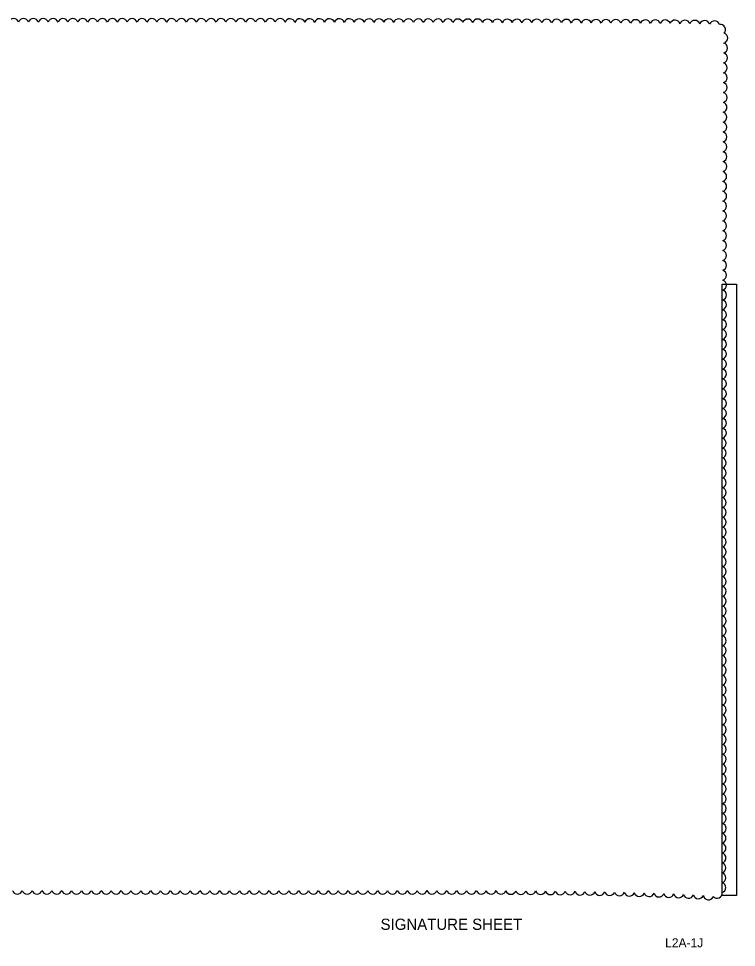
# Model space of a CAD drawing. Extents: x -811 to 10319, y -2309 to 9962.
# Drawn here: x -803.29 to -795.29, y -2309.09 to -2298.74 of the extents above; entities that cross this region are included whole.
import ezdxf

# ---------------------------------------------------------------- set-up
doc = ezdxf.new("R2010")
doc.units = 0
for name, color, linetype in [('AdhocPoint_dp', 7, 'Continuous'), ('PlotBorder_dp', 7, 'Continuous'), ('ScratchEle_dp', 7, 'Continuous'), ('SheetLines_dp', 7, 'Continuous')]:
    doc.layers.add(name, color=color, linetype=linetype)

msp = doc.modelspace()

# ---------------------------------------------------------------- linework, layer by layer
at = {"layer": 'AdhocPoint_dp'}
msp.add_lwpolyline([(-795.444, -2301.701), (-795.287, -2301.701), (-795.287, -2308.512), (-795.444, -2308.512)], close=True, dxfattribs=at)
at = {"layer": 'ScratchEle_dp'}
for centre, start, end in [((-803.344, -2298.801), 17.5, 162.5), ((-803.234, -2298.801), 17.5, 162.5), ((-803.124, -2298.801), 17.4999, 162.4999), ((-803.014, -2298.801), 17.4985, 162.4985), ((-802.904, -2298.801), 17.4968, 162.4968), ((-802.794, -2298.801), 17.495, 162.495), ((-802.684, -2298.801), 17.4932, 162.4932), ((-802.574, -2298.801), 17.4913, 162.4913), ((-802.464, -2298.801), 17.4894, 162.4894), ((-802.354, -2298.801), 17.4875, 162.4875), ((-802.243, -2298.801), 17.4855, 162.4855), ((-802.133, -2298.801), 17.4835, 162.4835), ((-802.023, -2298.801), 17.4814, 162.4814), ((-801.913, -2298.801), 17.4792, 162.4792), ((-801.803, -2298.801), 17.477, 162.477), ((-801.693, -2298.802), 17.4748, 162.4748), ((-801.583, -2298.802), 17.4725, 162.4725), ((-801.473, -2298.802), 17.4701, 162.4701), ((-801.363, -2298.802), 17.4676, 162.4676), ((-801.253, -2298.802), 17.4651, 162.4651), ((-801.143, -2298.802), 17.4625, 162.4625), ((-801.033, -2298.802), 17.4599, 162.4599), ((-800.923, -2298.802), 17.4571, 162.4571), ((-800.813, -2298.802), 17.4543, 162.4543), ((-800.703, -2298.802), 17.4514, 162.4514), ((-800.593, -2298.802), 17.4484, 162.4484), ((-800.483, -2298.802), 17.4453, 162.4453), ((-800.373, -2298.802), 17.4421, 162.4421), ((-800.263, -2298.803), 17.4388, 162.4388), ((-800.153, -2298.803), 17.4354, 162.4354), ((-800.043, -2298.803), 17.4318, 162.4318), ((-799.933, -2298.803), 17.4281, 162.4281), ((-799.823, -2298.803), 17.4243, 162.4243), ((-799.712, -2298.803), 17.4204, 162.4204), ((-799.602, -2298.803), 17.4162, 162.4162), ((-799.492, -2298.804), 17.412, 162.412), ((-799.382, -2298.804), 17.4075, 162.4075), ((-799.272, -2298.804), 17.4029, 162.4029), ((-799.162, -2298.804), 17.398, 162.398), ((-799.052, -2298.804), 17.3929, 162.3929), ((-798.942, -2298.805), 17.3876, 162.3876), ((-798.832, -2298.805), 17.3821, 162.3821), ((-798.722, -2298.805), 17.3762, 162.3762), ((-798.612, -2298.805), 17.3701, 162.3701), ((-798.502, -2298.805), 17.3636, 162.3636), ((-798.392, -2298.806), 17.3568, 162.3568), ((-798.282, -2298.806), 17.3496, 162.3496), ((-798.172, -2298.806), 17.342, 162.342), ((-798.062, -2298.807), 17.3339, 162.3339), ((-797.952, -2298.807), 17.3253, 162.3253), ((-797.842, -2298.807), 17.3161, 162.3161), ((-797.732, -2298.808), 17.3062, 162.3062), ((-797.622, -2298.808), 17.2956, 162.2956), ((-797.512, -2298.808), 17.2842, 162.2842), ((-797.402, -2298.809), 17.2719, 162.2719), ((-797.292, -2298.809), 17.2584, 162.2584), ((-797.182, -2298.81), 17.2438, 162.2438), ((-797.072, -2298.81), 17.2277, 162.2277), ((-796.961, -2298.811), 17.2099, 162.2099), ((-796.851, -2298.811), 17.1901, 162.1901), ((-796.741, -2298.812), 17.1679, 162.1679), ((-796.631, -2298.813), 17.1427, 162.1427), ((-796.521, -2298.813), 17.1138, 162.1138), ((-796.411, -2298.814), 17.0803, 162.0803), ((-796.301, -2298.815), 17.0406, 162.0406), ((-796.191, -2298.816), 16.9927, 161.9927), ((-796.081, -2298.817), 16.9334, 161.9334), ((-795.971, -2298.818), 16.857, 161.857), ((-795.861, -2298.819), 16.7534, 161.7534), ((-795.751, -2298.821), 16.6013, 161.6013), ((-795.641, -2298.823), 16.3442, 161.3442), ((-795.531, -2298.826), 15.7356, 160.7356), ((-795.465, -2298.867), 316.2708, 101.2708), ((-795.442, -2298.961), 286.1724, 71.1724), ((-795.444, -2299.071), 286.5791, 71.5791), ((-795.445, -2299.181), 286.7773, 71.7773), ((-795.447, -2299.292), 286.9008, 71.9008), ((-795.448, -2299.402), 286.9872, 71.9872), ((-795.449, -2299.512), 287.0522, 72.0522), ((-795.449, -2299.622), 287.1032, 72.1032), ((-795.45, -2299.732), 287.1448, 72.1448), ((-795.451, -2299.842), 287.1794, 72.1794), ((-795.451, -2299.952), 287.2089, 72.2089), ((-795.452, -2300.062), 287.2343, 72.2343), ((-795.452, -2300.172), 287.2566, 72.2566), ((-795.453, -2300.282), 287.2764, 72.2764), ((-795.453, -2300.392), 287.294, 72.294), ((-795.454, -2300.502), 287.3099, 72.3099), ((-795.454, -2300.612), 287.3243, 72.3243), ((-795.454, -2300.722), 287.3374, 72.3374), ((-795.455, -2300.832), 287.3494, 72.3494), ((-795.455, -2300.942), 287.3605, 72.3605), ((-795.455, -2301.052), 287.3708, 72.3708), ((-795.455, -2301.162), 287.3803, 72.3803), ((-795.456, -2301.272), 287.3892, 72.3892), ((-795.456, -2301.383), 287.3975, 72.3975), ((-795.456, -2301.493), 287.4053, 72.4053), ((-795.456, -2301.603), 287.4126, 72.4126), ((-795.456, -2301.713), 287.4195, 72.4195), ((-795.456, -2301.823), 287.426, 72.426), ((-795.457, -2301.933), 287.4322, 72.4322), ((-795.457, -2302.043), 287.438, 72.438), ((-795.457, -2302.153), 287.4436, 72.4436), ((-795.457, -2302.263), 287.4489, 72.4489), ((-795.457, -2302.373), 287.4539, 72.4539), ((-795.457, -2302.483), 287.4588, 72.4588), ((-795.457, -2302.593), 287.4634, 72.4634), ((-795.457, -2302.703), 287.4678, 72.4678), ((-795.457, -2302.813), 287.472, 72.472), ((-795.457, -2302.923), 287.476, 72.476), ((-795.457, -2303.033), 287.4799, 72.4799), ((-795.457, -2303.143), 287.4837, 72.4837), ((-795.457, -2303.253), 287.4873, 72.4873), ((-795.457, -2303.363), 287.4907, 72.4907), ((-795.458, -2303.473), 287.4941, 72.4941), ((-795.458, -2303.583), 287.4973, 72.4973), ((-795.458, -2303.693), 287.4996, 72.4996), ((-795.458, -2303.804), 287.4988, 72.4988), ((-795.458, -2303.914), 287.4977, 72.4977), ((-795.458, -2304.024), 287.4966, 72.4966), ((-795.458, -2304.134), 287.4954, 72.4954), ((-795.458, -2304.244), 287.4942, 72.4942), ((-795.458, -2304.354), 287.4929, 72.4929), ((-795.458, -2304.464), 287.4916, 72.4916), ((-795.458, -2304.574), 287.4903, 72.4903), ((-795.458, -2304.684), 287.4888, 72.4888), ((-795.458, -2304.794), 287.4874, 72.4874), ((-795.458, -2304.904), 287.4858, 72.4858), ((-795.458, -2305.014), 287.4842, 72.4842), ((-795.458, -2305.124), 287.4825, 72.4825), ((-795.458, -2305.234), 287.4807, 72.4807), ((-795.458, -2305.344), 287.4788, 72.4788), ((-795.458, -2305.454), 287.4768, 72.4768), ((-795.458, -2305.564), 287.4747, 72.4747), ((-795.458, -2305.674), 287.4725, 72.4725), ((-795.458, -2305.784), 287.4702, 72.4702), ((-795.458, -2305.894), 287.4677, 72.4677), ((-795.458, -2306.004), 287.4651, 72.4651), ((-795.458, -2306.114), 287.4622, 72.4622), ((-795.458, -2306.224), 287.4592, 72.4592), ((-795.458, -2306.335), 287.456, 72.456), ((-795.458, -2306.445), 287.4525, 72.4525), ((-795.459, -2306.555), 287.4487, 72.4487), ((-795.459, -2306.665), 287.4446, 72.4446), ((-795.459, -2306.775), 287.4401, 72.4401), ((-795.459, -2306.885), 287.4351, 72.4351), ((-795.459, -2306.995), 287.4296, 72.4296), ((-795.459, -2307.105), 287.4236, 72.4236), ((-795.459, -2307.215), 287.4167, 72.4167), ((-795.459, -2307.325), 287.409, 72.409), ((-795.46, -2307.435), 287.4001, 72.4001), ((-795.46, -2307.545), 287.3897, 72.3897), ((-795.46, -2307.655), 287.3775, 72.3775), ((-795.46, -2307.765), 287.3627, 72.3627), ((-795.461, -2307.875), 287.3443, 72.3443), ((-795.461, -2307.985), 287.3206, 72.3206), ((-795.461, -2308.095), 287.2884, 72.2884), ((-795.462, -2308.205), 287.2408, 72.2408), ((-795.462, -2308.315), 287.1595, 72.1595), ((-795.463, -2308.425), 286.9603, 71.9603), ((-803.303, -2308.44), 197.5, 342.5), ((-803.193, -2308.44), 197.5, 342.5), ((-803.083, -2308.44), 197.5, 342.5), ((-802.973, -2308.44), 197.5, 342.5), ((-802.863, -2308.44), 197.5, 342.5), ((-802.753, -2308.44), 197.5, 342.5), ((-802.643, -2308.44), 197.5, 342.5), ((-802.533, -2308.44), 197.5, 342.5), ((-802.422, -2308.44), 197.5, 342.5), ((-802.312, -2308.44), 197.5, 342.5), ((-802.202, -2308.44), 197.5, 342.5), ((-802.092, -2308.44), 197.5, 342.5), ((-801.982, -2308.44), 197.5, 342.5), ((-801.872, -2308.44), 197.5, 342.5), ((-801.762, -2308.44), 197.5, 342.5), ((-801.652, -2308.44), 197.5, 342.5), ((-801.542, -2308.44), 197.5, 342.5), ((-801.432, -2308.44), 197.5, 342.5), ((-801.322, -2308.44), 197.5, 342.5), ((-801.212, -2308.44), 197.5, 342.5), ((-801.102, -2308.44), 197.5, 342.5), ((-800.992, -2308.44), 197.5, 342.5), ((-800.882, -2308.44), 197.5, 342.5), ((-800.772, -2308.44), 197.5, 342.5), ((-800.662, -2308.44), 197.5, 342.5), ((-800.552, -2308.44), 197.5, 342.5), ((-800.442, -2308.44), 197.5, 342.5), ((-800.332, -2308.44), 197.5, 342.5), ((-800.222, -2308.44), 197.5, 342.5), ((-800.112, -2308.44), 197.5, 342.5), ((-800.002, -2308.44), 197.5, 342.5), ((-799.891, -2308.44), 197.5, 342.5), ((-799.781, -2308.44), 197.5, 342.5), ((-799.671, -2308.44), 197.5, 342.5), ((-799.561, -2308.44), 197.5, 342.5), ((-799.451, -2308.44), 197.5, 342.5), ((-799.341, -2308.44), 197.5, 342.5), ((-799.231, -2308.44), 197.5, 342.5), ((-799.121, -2308.44), 197.5, 342.5), ((-799.011, -2308.44), 197.5, 342.5), ((-798.901, -2308.44), 197.5, 342.5), ((-798.791, -2308.44), 197.5, 342.5), ((-798.681, -2308.44), 197.5, 342.5), ((-798.571, -2308.44), 197.4875, 342.4875), ((-798.461, -2308.44), 197.4461, 342.4461), ((-798.351, -2308.44), 197.4016, 342.4016), ((-798.241, -2308.44), 197.3547, 342.3547), ((-798.131, -2308.44), 197.3053, 342.3053), ((-798.021, -2308.441), 197.2532, 342.2532), ((-797.911, -2308.441), 197.198, 342.198), ((-797.801, -2308.442), 197.1394, 342.1394), ((-797.69, -2308.443), 197.0771, 342.0771), ((-797.58, -2308.444), 197.0107, 342.0107), ((-797.47, -2308.445), 196.9397, 341.9397), ((-797.36, -2308.446), 196.8636, 341.8636), ((-797.25, -2308.447), 196.7816, 341.7816), ((-797.14, -2308.448), 196.6931, 341.6931), ((-797.03, -2308.45), 196.597, 341.597), ((-796.92, -2308.452), 196.4924, 341.4924), ((-796.81, -2308.454), 196.3777, 341.3777), ((-796.7, -2308.456), 196.2513, 341.2513), ((-796.59, -2308.459), 196.111, 341.111), ((-796.48, -2308.462), 195.9541, 340.9541), ((-796.37, -2308.465), 195.8088, 340.8088), ((-796.26, -2308.468), 195.6685, 340.6685), ((-796.15, -2308.472), 195.4928, 340.4928), ((-796.04, -2308.476), 195.2636, 340.2636), ((-795.93, -2308.48), 194.9466, 339.9466), ((-795.82, -2308.486), 194.4656, 339.4656), ((-795.709, -2308.492), 193.5975, 338.5975), ((-795.599, -2308.503), 190.9865, 335.9865), ((-795.504, -2308.487), 222.0186, 7.0186)]:
    msp.add_arc(centre, 0.0577, start, end, dxfattribs=at)

# ---------------------------------------------------------------- texts
at = {"layer": 'PlotBorder_dp'}
msp.add_text('       SIGNATURE SHEET         ', height=0.125, dxfattribs=at).set_placement((-799.579, -2308.896))
at = {"layer": 'SheetLines_dp'}
msp.add_text('L2A-1J', height=0.1, dxfattribs=at).set_placement((-796.081, -2309.09))

doc.saveas('drawing.dxf')
